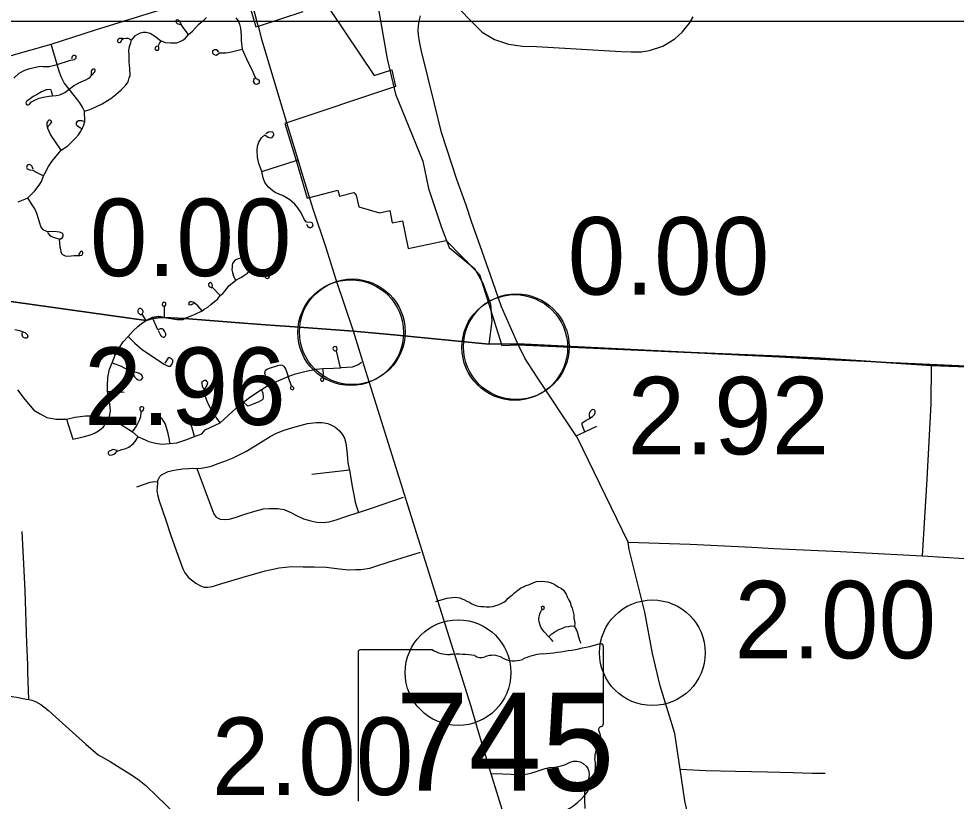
# Model space of a CAD drawing. Extents: x 1729596 to 1934326, y 644115 to 911751.
# Drawn here: x 1788422 to 1801727, y 773601 to 784711 of the extents above; entities that cross this region are included whole.
import ezdxf

# ---------------------------------------------------------------- set-up
doc = ezdxf.new("R2010")
doc.units = 0
for name, color, linetype in [('Default', 7, 'Continuous'), ('GM_X_City_Street', 7, 'Continuous'), ('GM_X_Corporation', 7, 'Continuous'), ('GM_X_County', 7, 'Continuous'), ('GM_X_State_Route', 7, 'Continuous'), ('GM_X_State_Shield', 7, 'Continuous'), ('GM_X_Township', 7, 'Continuous'), ('SC_Scratch1', 7, 'Continuous')]:
    doc.layers.add(name, color=color, linetype=linetype)

msp = doc.modelspace()

# ---------------------------------------------------------------- linework, layer by layer
at = {"layer": 'Default'}
for centre in [(1793134, 780255), (1793134, 780255), (1793156, 780266), (1795462, 780044), (1795462, 780044), (1795483, 780055), (1797415, 775709), (1794657, 775427)]:
    msp.add_circle(centre, 750, dxfattribs=at)
at = {"layer": 'GM_X_City_Street'}
for points in [[(1786111, 783497), (1786161, 783513), (1786229, 783545), (1786322, 783619), (1786378, 783661), (1786427, 783697), (1786487, 783730), (1786569, 783756), (1786939, 783865), (1787087, 783901), (1787342, 783978), (1787586, 784047), (1787860, 784131), (1788123, 784193), (1788314, 784188), (1788881, 784351), (1789511, 784554), (1790304, 784798), (1790967, 785005), (1791652, 785213)], [(1789356, 783400), (1789433, 783423), (1789518, 783458), (1789607, 783505), (1789681, 783549), (1789727, 783577), (1789801, 783637), (1789878, 783702), (1789938, 783762), (1789973, 783813), (1789991, 783871), (1790003, 783904), (1789998, 784006), (1789989, 784098), (1789987, 784196), (1789984, 784256), (1789995, 784319), (1790012, 784368), (1790024, 784407), (1790048, 784434), (1790080, 784471), (1790114, 784494), (1790151, 784511), (1790187, 784519), (1790230, 784520), (1790289, 784507), (1790365, 784458), (1790421, 784413), (1790445, 784397), (1790501, 784374), (1790577, 784367), (1790618, 784368), (1790665, 784369), (1790714, 784389), (1790753, 784408), (1790789, 784437), (1790831, 784488), (1790887, 784537), (1790931, 784580), (1790973, 784629), (1791012, 784663), (1791048, 784692), (1791085, 784728)], [(1791504, 784726), (1791535, 784683), (1791553, 784636), (1791567, 784578), (1791577, 784474), (1791577, 784402), (1791592, 784280), (1791630, 784195), (1791679, 784092), (1791710, 784030), (1791743, 783957), (1791772, 783888), (1791788, 783862), (1791815, 783852), (1791832, 783838), (1791835, 783820), (1791833, 783798), (1791819, 783786), (1791801, 783778), (1791779, 783784), (1791766, 783795), (1791755, 783818), (1791770, 783872)], [(1790831, 784488), (1790754, 784589), (1790727, 784629), (1790719, 784654), (1790709, 784674), (1790689, 784691), (1790668, 784694), (1790656, 784690), (1790651, 784682), (1790655, 784658), (1790669, 784642), (1790700, 784636), (1790722, 784629)], [(1788415, 782110), (1788510, 782150), (1788551, 782167), (1788652, 782266), (1788713, 782346), (1788743, 782401), (1788772, 782479), (1788791, 782516), (1788844, 782611), (1788894, 782686), (1788952, 782759), (1789024, 782843), (1789118, 782906), (1789174, 782964), (1789228, 783014), (1789269, 783061), (1789291, 783092), (1789323, 783148), (1789348, 783207), (1789359, 783254), (1789356, 783400), (1789329, 783456), (1789290, 783516), (1789263, 783556), (1789137, 783711), (1789068, 783802), (1789026, 783888), (1788990, 783979), (1788967, 784062), (1788881, 784351)], [(1789900, 784432), (1789878, 784431), (1789851, 784431), (1789837, 784422), (1789826, 784407), (1789825, 784390), (1789837, 784376), (1789852, 784373), (1789871, 784380), (1789882, 784401), (1789894, 784423), (1789908, 784431), (1789946, 784435), (1789969, 784434), (1789995, 784424), (1790024, 784407)], [(1790398, 784323), (1790374, 784319), (1790361, 784308), (1790356, 784294), (1790355, 784286), (1790361, 784272), (1790382, 784261), (1790401, 784264), (1790408, 784278), (1790411, 784302), (1790407, 784330), (1790419, 784361), (1790445, 784397)], [(1788352, 783865), (1788430, 783939), (1788507, 783981), (1788580, 784005), (1788703, 784035), (1788744, 784037), (1788768, 784035), (1788856, 784035), (1788967, 784062), (1789157, 784124), (1789215, 784133), (1789239, 784154), (1789239, 784170), (1789232, 784185), (1789212, 784191), (1789194, 784189), (1789182, 784173), (1789170, 784140)], [(1791262, 784238), (1791242, 784262), (1791227, 784269), (1791213, 784271), (1791200, 784269), (1791186, 784259), (1791174, 784251), (1791173, 784227), (1791176, 784218), (1791184, 784207), (1791203, 784197), (1791226, 784196), (1791246, 784210), (1791269, 784228), (1791359, 784229), (1791440, 784241), (1791592, 784280)], [(1788901, 783628), (1788892, 783669), (1788888, 783685), (1788876, 783703), (1788857, 783708), (1788826, 783704), (1788811, 783702), (1788744, 783671), (1788683, 783636), (1788626, 783605), (1788583, 783575), (1788533, 783534), (1788525, 783517), (1788528, 783498), (1788538, 783490), (1788554, 783491), (1788573, 783496), (1788604, 783531), (1788641, 783551), (1788670, 783566), (1788712, 783583), (1788749, 783594), (1788795, 783604), (1788851, 783613), (1788896, 783615), (1788953, 783619), (1789007, 783630), (1789075, 783665), (1789137, 783711), (1789197, 783758), (1789274, 783799), (1789340, 783830), (1789376, 783844), (1789415, 783865), (1789430, 783879), (1789455, 783906), (1789477, 783929), (1789488, 783941), (1789502, 783956), (1789509, 783970), (1789506, 783986), (1789493, 783995), (1789477, 783995), (1789463, 783989), (1789455, 783976), (1789452, 783961), (1789452, 783912)], [(1789024, 782843), (1788875, 783066), (1788835, 783151), (1788841, 783186), (1788870, 783216), (1788882, 783231), (1788889, 783239), (1788890, 783244), (1788889, 783250), (1788885, 783255), (1788876, 783263), (1788865, 783269), (1788853, 783269), (1788842, 783262), (1788833, 783251), (1788822, 783232), (1788820, 783215), (1788820, 783194), (1788830, 783153)], [(1789323, 783148), (1789300, 783159), (1789276, 783173), (1789246, 783193), (1789240, 783211), (1789244, 783234), (1789254, 783257), (1789269, 783265), (1789293, 783266), (1789315, 783264), (1789359, 783254)], [(1791871, 782541), (1791831, 782654), (1791812, 782744), (1791806, 782842), (1791812, 782904), (1791831, 782961), (1791865, 783021), (1791917, 783061), (1791963, 783032), (1791992, 783019), (1792019, 783026), (1792042, 783057), (1792044, 783072), (1792027, 783099), (1791998, 783107), (1791965, 783101), (1791927, 783076)], [(1788625, 782574), (1788616, 782601), (1788611, 782614), (1788596, 782633), (1788576, 782642), (1788555, 782639), (1788540, 782627), (1788533, 782599), (1788542, 782581), (1788557, 782573), (1788575, 782568), (1788628, 782561), (1788670, 782534), (1788772, 782479)], [(1791871, 782541), (1792361, 782698), (1792387, 782707)], [(1792505, 781794), (1792527, 781763), (1792545, 781746), (1792569, 781746), (1792586, 781757), (1792599, 781776), (1792597, 781796), (1792586, 781813), (1792570, 781819), (1792508, 781822), (1792477, 781856), (1792445, 781926), (1792422, 781971), (1792385, 782027), (1792341, 782080), (1792271, 782141), (1792177, 782198), (1792061, 782246), (1792027, 782268), (1791966, 782318), (1791917, 782384), (1791892, 782451), (1791871, 782541)], [(1788829, 781675), (1788857, 781639), (1788882, 781622), (1788912, 781608), (1788960, 781594), (1788995, 781586), (1789019, 781588), (1789038, 781599), (1789048, 781614), (1789051, 781624), (1789052, 781639), (1789051, 781649), (1789047, 781656), (1789037, 781666), (1789001, 781680), (1788919, 781689), (1788828, 781685), (1788770, 781715), (1788737, 781762), (1788721, 781810), (1788703, 781869), (1788683, 781930), (1788665, 781982), (1788641, 782025), (1788604, 782084), (1788551, 782167)], [(1788995, 781586), (1788999, 781521), (1789006, 781474), (1789014, 781438), (1789020, 781402), (1789031, 781380), (1789043, 781362), (1789061, 781352), (1789082, 781346), (1789118, 781342), (1789165, 781345), (1789209, 781349), (1789288, 781349), (1789316, 781352), (1789328, 781362), (1789333, 781381), (1789331, 781394), (1789325, 781403), (1789311, 781409), (1789300, 781404), (1789293, 781396), (1789283, 781385), (1789270, 781359)], [(1791600, 781309), (1791613, 781339), (1791616, 781385), (1791619, 781458)], [(1790776, 780453), (1790904, 780507), (1790925, 780515), (1791023, 780562), (1791056, 780587), (1791108, 780616), (1791150, 780652), (1791250, 780736), (1791280, 780781), (1791317, 780810), (1791351, 780849), (1791406, 780917), (1791502, 780999), (1791572, 781038), (1791610, 781059), (1791668, 781101), (1791693, 781125), (1791708, 781142), (1791712, 781181), (1791708, 781209), (1791698, 781236), (1791677, 781269), (1791639, 781296), (1791617, 781304), (1791600, 781309), (1791572, 781311), (1791536, 781302), (1791503, 781286), (1791481, 781267), (1791458, 781236), (1791452, 781219), (1791449, 781190), (1791446, 781148), (1791454, 781106), (1791470, 781058), (1791500, 781004)], [(1791708, 781142), (1791852, 781081), (1791902, 781060), (1791934, 781030), (1791949, 781025), (1791961, 781026), (1791973, 781033), (1791982, 781049), (1791983, 781068), (1791975, 781084), (1791949, 781089), (1791902, 781070)], [(1791280, 780781), (1791168, 780898), (1791173, 780923), (1791166, 780944), (1791154, 780959), (1791139, 780966), (1791129, 780962), (1791120, 780954), (1791113, 780936), (1791119, 780916), (1791136, 780905), (1791163, 780892)], [(1790229, 780426), (1790175, 780517), (1790184, 780538), (1790186, 780546), (1790188, 780554), (1790181, 780568), (1790178, 780577), (1790174, 780583), (1790166, 780589), (1790160, 780593), (1790156, 780596), (1790151, 780599), (1790142, 780598), (1790134, 780595), (1790126, 780590), (1790121, 780585), (1790116, 780579), (1790112, 780570), (1790113, 780562), (1790113, 780557), (1790112, 780550), (1790113, 780545), (1790116, 780539), (1790120, 780531), (1790126, 780526), (1790134, 780521), (1790151, 780514), (1790171, 780514)], [(1790491, 780471), (1790493, 780620), (1790512, 780651), (1790512, 780663), (1790508, 780676), (1790495, 780682), (1790479, 780685), (1790465, 780677), (1790456, 780657), (1790460, 780644), (1790466, 780638), (1790484, 780624)], [(1791023, 780562), (1790964, 780636), (1790914, 780678), (1790896, 780688), (1790873, 780690), (1790854, 780690), (1790840, 780682), (1790831, 780667), (1790837, 780655), (1790855, 780651), (1790874, 780654), (1790888, 780661), (1790907, 780670)], [(1789704, 779043), (1789715, 779089), (1789724, 779146), (1789722, 779192), (1789709, 779277), (1789682, 779417), (1789680, 779501), (1789687, 779615), (1789709, 779735), (1789747, 779826), (1789795, 779948), (1789843, 780028), (1789906, 780123), (1789973, 780198), (1790046, 780282), (1790110, 780341), (1790166, 780385), (1790229, 780426), (1790323, 780455), (1790403, 780463), (1790491, 780471), (1790665, 780443), (1790696, 780441), (1790728, 780441), (1790750, 780442), (1790776, 780453)], [(1790400, 780283), (1790418, 780247), (1790434, 780217), (1790446, 780201), (1790471, 780188), (1790486, 780189), (1790493, 780196), (1790505, 780209), (1790508, 780220), (1790508, 780235), (1790500, 780254), (1790491, 780277), (1790475, 780298), (1790458, 780306), (1790428, 780307), (1790395, 780294), (1790323, 780455)], [(1788369, 780298), (1788433, 780283), (1788485, 780266), (1788520, 780252), (1788540, 780230), (1788546, 780218), (1788551, 780205), (1788546, 780189), (1788545, 780184), (1788532, 780177), (1788521, 780174), (1788515, 780174), (1788488, 780185), (1788482, 780196), (1788475, 780211), (1788472, 780225), (1788470, 780242), (1788474, 780262)], [(1789973, 780198), (1790068, 780107), (1790178, 780010), (1790488, 779809), (1790541, 779778), (1790574, 779776), (1790593, 779804), (1790609, 779841), (1790609, 779864), (1790587, 779889), (1790556, 779901), (1790539, 779887), (1790496, 779823)], [(1792988, 779756), (1792931, 779997), (1792938, 780010), (1792939, 780025), (1792937, 780041), (1792932, 780051), (1792921, 780055), (1792906, 780056), (1792894, 780052), (1792888, 780049), (1792884, 780043), (1792882, 780030), (1792886, 780020), (1792890, 780010), (1792899, 780001), (1792909, 779998), (1792929, 779997)], [(1789747, 779826), (1789876, 779777), (1789971, 779727), (1790031, 779683), (1790065, 779628), (1790092, 779598), (1790118, 779583), (1790147, 779580), (1790165, 779589), (1790181, 779612), (1790179, 779637), (1790166, 779654), (1790136, 779672), (1790095, 779686), (1790047, 779691)], [(1791983, 779520), (1791922, 779641), (1791919, 779660), (1791913, 779682), (1791918, 779697), (1791924, 779721), (1791948, 779737), (1791982, 779752), (1792099, 779789), (1792137, 779795), (1792165, 779794), (1792185, 779775), (1792200, 779756), (1792211, 779733), (1792245, 779631)], [(1792997, 779757), (1793077, 779763), (1793160, 779770), (1793235, 779797), (1793288, 779833)], [(1801247, 777085), (1801313, 778173), (1801372, 779244), (1801375, 779790)], [(1788405, 779442), (1788510, 779307), (1788637, 779155), (1788724, 779103), (1788822, 779051), (1788950, 779024), (1789102, 779024), (1789220, 779052), (1789372, 779073), (1789476, 779073), (1789597, 779060), (1789651, 779051), (1789704, 779043), (1789793, 779002), (1789904, 778933), (1789954, 778896), (1790035, 778844), (1790115, 778777), (1790173, 778753), (1790269, 778708), (1790361, 778684), (1790451, 778673), (1790566, 778679), (1790667, 778689), (1790810, 778738), (1790917, 778780), (1791021, 778816), (1791068, 778874), (1791283, 778975), (1791509, 779180), (1791555, 779219), (1791610, 779266), (1791704, 779339), (1791865, 779449), (1791983, 779520), (1792245, 779631), (1792350, 779669), (1792502, 779709), (1792643, 779738), (1792740, 779744), (1792891, 779750), (1792976, 779755), (1792988, 779756), (1792997, 779757)], [(1792739, 779614), (1792723, 779610), (1792711, 779602), (1792707, 779592), (1792709, 779577), (1792719, 779565), (1792728, 779564), (1792738, 779567), (1792747, 779576), (1792751, 779587), (1792750, 779596), (1792748, 779603), (1792739, 779614), (1792749, 779679), (1792740, 779744)], [(1791283, 778975), (1791186, 779107), (1791153, 779161), (1791126, 779215), (1791092, 779289), (1791069, 779364), (1791056, 779406), (1791052, 779454), (1791071, 779469), (1791085, 779490), (1791098, 779514), (1791105, 779547), (1791093, 779562), (1791080, 779574), (1791057, 779577), (1791046, 779570), (1791030, 779557), (1791018, 779545), (1791019, 779531), (1791025, 779496), (1791031, 779486), (1791050, 779454)], [(1791610, 779266), (1791513, 779380), (1791495, 779419), (1791490, 779457), (1791488, 779505), (1791519, 779531), (1791531, 779542), (1791546, 779561), (1791571, 779602), (1791570, 779613), (1791560, 779631), (1791545, 779639), (1791527, 779639), (1791517, 779636), (1791502, 779628), (1791490, 779609), (1791475, 779582), (1791473, 779556), (1791474, 779531), (1791486, 779505)], [(1792291, 779492), (1792282, 779485), (1792279, 779474), (1792280, 779460), (1792284, 779451), (1792306, 779443), (1792316, 779447), (1792320, 779454), (1792324, 779464), (1792324, 779473), (1792317, 779482), (1792311, 779487), (1792302, 779492), (1792291, 779492), (1792245, 779631)], [(1789682, 779417), (1789776, 779420), (1789920, 779407)], [(1791610, 779266), (1791669, 779216), (1791690, 779221), (1791717, 779229), (1791827, 779271), (1791892, 779311), (1791897, 779340), (1791893, 779389), (1791865, 779449)], [(1790035, 778844), (1790094, 778927), (1790132, 779000), (1790155, 779063), (1790161, 779120), (1790163, 779133), (1790181, 779144), (1790193, 779160), (1790196, 779177), (1790196, 779185), (1790189, 779195), (1790175, 779202), (1790161, 779203), (1790146, 779197), (1790140, 779183), (1790140, 779168), (1790156, 779135)], [(1790917, 778780), (1790877, 778915), (1790767, 779125), (1790752, 779171)], [(1796458, 778846), (1796426, 778917), (1796419, 778943), (1796418, 778975), (1796469, 779005), (1796511, 779030), (1796566, 779062), (1796593, 779090), (1796601, 779115), (1796604, 779144), (1796589, 779157), (1796569, 779165), (1796550, 779155), (1796534, 779140), (1796518, 779105), (1796519, 779073), (1796526, 779038)], [(1789102, 779024), (1789192, 778742), (1789338, 778775), (1789440, 778805), (1789505, 778830), (1789556, 778860), (1789594, 778887), (1789624, 778916), (1789639, 778938), (1789646, 778970), (1789651, 779051)], [(1790566, 778679), (1790564, 778733), (1790544, 778820), (1790503, 778953), (1790458, 779032), (1790398, 779094)], [(1790099, 778063), (1790288, 778133), (1790322, 778136), (1790355, 778139), (1790391, 778134), (1790401, 778164), (1790408, 778184), (1790424, 778212), (1790447, 778235), (1790496, 778260), (1790542, 778283), (1790606, 778297), (1790655, 778308), (1790745, 778322), (1790833, 778326), (1790891, 778331), (1790951, 778327), (1791011, 778332), (1791088, 778342), (1791156, 778360), (1791237, 778391), (1791346, 778428), (1791465, 778477), (1791550, 778517), (1791645, 778567), (1791779, 778646), (1791891, 778716), (1791991, 778779), (1792072, 778822), (1792173, 778863), (1792314, 778908), (1792519, 778963), (1792642, 778980), (1792730, 778980), (1792809, 778966), (1792859, 778941), (1792910, 778918), (1792975, 778860), (1793014, 778811), (1793044, 778754), (1793064, 778684), (1793076, 778577), (1793087, 778469), (1793092, 778412), (1793113, 778316), (1793115, 778305), (1793141, 778155), (1793157, 778048), (1793179, 777953), (1793198, 777849), (1793216, 777788), (1793246, 777702)], [(1796333, 778788), (1796458, 778846), (1796628, 778926)], [(1789817, 778580), (1789783, 778592), (1789759, 778593), (1789727, 778583), (1789703, 778569), (1789692, 778556), (1789692, 778543), (1789695, 778531), (1789704, 778520), (1789716, 778514), (1789746, 778519), (1789785, 778534), (1789821, 778572), (1789848, 778582), (1789887, 778594), (1789941, 778609), (1789983, 778630), (1790045, 778676), (1790074, 778708), (1790115, 778777)], [(1790951, 778327), (1791171, 777731), (1791194, 777674), (1791223, 777634), (1791282, 777606), (1791336, 777599), (1791408, 777607), (1791495, 777628), (1791618, 777671), (1791771, 777721), (1791894, 777752), (1791982, 777758), (1792100, 777757), (1792190, 777743), (1792285, 777700), (1792366, 777658), (1792463, 777613), (1792568, 777582), (1792652, 777562), (1792742, 777558), (1792826, 777567), (1792929, 777595), (1793062, 777643), (1793238, 777699), (1793246, 777702), (1793442, 777768), (1793882, 777919)], [(1792584, 778243), (1793115, 778305)], [(1790391, 778134), (1790387, 778051), (1790382, 778011), (1790391, 777956), (1790414, 777867), (1790468, 777716), (1790509, 777594), (1790578, 777386), (1790658, 777159), (1790751, 776900), (1790777, 776845), (1790832, 776780), (1790937, 776695), (1791003, 776661), (1791054, 776642), (1791106, 776642), (1791170, 776649), (1791259, 776676), (1791606, 776781), (1791919, 776873), (1792011, 776891), (1792118, 776916), (1792297, 776934), (1792459, 776931), (1792613, 776927), (1792783, 776923), (1792974, 776902), (1793100, 776887), (1793202, 776892), (1793276, 776890), (1793407, 776911), (1793502, 776942), (1793667, 776996), (1794123, 777139)], [(1788551, 775488), (1788549, 775542), (1788539, 775845), (1788512, 776595), (1788492, 777063), (1788470, 777429)], [(1797070, 777278), (1797953, 777250), (1798827, 777207), (1799137, 777189), (1800084, 777145), (1801247, 777085), (1801844, 777048), (1803558, 776945), (1803593, 776944)], [(1794341, 776439), (1794370, 776448), (1794451, 776472), (1794498, 776483), (1794535, 776490), (1794578, 776494), (1794616, 776497), (1794651, 776494), (1794683, 776488), (1794712, 776477), (1794740, 776463), (1794779, 776444), (1794818, 776427), (1794842, 776409), (1794875, 776396), (1794909, 776382), (1794948, 776373), (1794981, 776365), (1795025, 776364), (1795058, 776361), (1795107, 776362), (1795149, 776364), (1795195, 776381), (1795228, 776391), (1795269, 776409), (1795306, 776427), (1795338, 776453), (1795366, 776482), (1795402, 776515), (1795430, 776533), (1795459, 776561), (1795507, 776597), (1795544, 776625), (1795575, 776640), (1795624, 776663), (1795670, 776678), (1795709, 776696), (1795771, 776719), (1795838, 776725), (1795886, 776722), (1795932, 776715), (1795976, 776701), (1796020, 776682), (1796065, 776656), (1796088, 776641), (1796124, 776622), (1796153, 776597), (1796171, 776568), (1796189, 776543), (1796207, 776505), (1796226, 776467), (1796246, 776429), (1796259, 776383), (1796277, 776343), (1796290, 776286), (1796298, 776247), (1796302, 776203), (1796308, 776160), (1796313, 776123), (1796311, 776089), (1796321, 776063), (1796331, 776039), (1796345, 776004), (1796365, 775935), (1796386, 775876), (1796399, 775845)], [(1784196, 776473), (1784304, 776457), (1784415, 776425), (1784775, 776295), (1785202, 776135), (1785945, 775831), (1786304, 775696), (1786590, 775596), (1786871, 775480), (1787181, 775362), (1787342, 775300), (1787411, 775274), (1787519, 775244), (1788001, 775154), (1788269, 775099), (1788392, 775079), (1788532, 775051)], [(1796007, 775869), (1795972, 775907), (1795944, 775934), (1795878, 776005), (1795852, 776042), (1795833, 776072), (1795820, 776102), (1795810, 776150), (1795805, 776187), (1795810, 776221), (1795817, 776259), (1795829, 776286), (1795840, 776313), (1795845, 776321), (1795860, 776324), (1795874, 776331), (1795882, 776338), (1795881, 776352), (1795879, 776360), (1795874, 776365), (1795868, 776368), (1795860, 776365), (1795852, 776365), (1795841, 776361), (1795838, 776356), (1795839, 776349), (1795842, 776339), (1795853, 776323)], [(1795944, 775934), (1795987, 775978), (1796044, 776015), (1796087, 776039), (1796128, 776052), (1796177, 776075), (1796228, 776084), (1796263, 776090), (1796311, 776089)], [(1788553, 775432), (1788551, 775488)], [(1788566, 775044), (1788553, 775432)], [(1788532, 775051), (1788566, 775044), (1788608, 775035), (1788660, 775017), (1788735, 774973), (1788780, 774943), (1788844, 774889), (1789044, 774708), (1789373, 774412), (1789549, 774260), (1789720, 774163), (1789825, 774100), (1789963, 774014), (1790039, 773965), (1790129, 773902), (1790224, 773825), (1790392, 773663), (1790495, 773565), (1790720, 773346), (1790822, 773244), (1790886, 773175)], [(1795129, 773990), (1795213, 773994), (1795290, 773990), (1795410, 773985), (1795490, 773982), (1795586, 773981), (1795646, 773988), (1795705, 774002), (1795780, 774029), (1795893, 774068), (1795951, 774080), (1796030, 774087), (1796079, 774093), (1796122, 774103), (1796174, 774120), (1796247, 774154), (1796297, 774168), (1796341, 774172), (1796388, 774162), (1796433, 774139), (1796473, 774101), (1796497, 774065), (1796514, 774021), (1796519, 773985), (1796515, 773940), (1796499, 773878), (1796465, 773780), (1796453, 773723), (1796450, 773664), (1796449, 773613), (1796456, 773496)], [(1797809, 774055), (1798172, 774036), (1798594, 774027), (1799049, 774019), (1799413, 774009), (1799687, 773999), (1799865, 774001)]]:
    msp.add_lwpolyline(points, dxfattribs=at)
at = {"layer": 'GM_X_Corporation'}
for points in [[(1791612, 785199), (1791786, 784595), (1791823, 784606), (1792459, 784812)], [(1792848, 784829), (1793468, 783905), (1793718, 783987), (1793735, 783894), (1793754, 783819), (1793758, 783789), (1793768, 783761), (1793769, 783748), (1792200, 783224), (1792361, 782698), (1792515, 782165), (1792950, 782279), (1792976, 782192), (1793178, 782246), (1793210, 782204), (1793248, 782040), (1793540, 781957), (1793687, 781987), (1793723, 781813), (1793870, 781843), (1793949, 781451), (1794488, 781561), (1794963, 781078), (1795276, 780074), (1795510, 780081), (1797967, 779971), (1799216, 779912), (1799794, 779878), (1803634, 779704)]]:
    msp.add_lwpolyline(points, dxfattribs=at)
at = {"layer": 'GM_X_County'}
for points in [[(1788100, 780727), (1790229, 780426), (1790317, 780468), (1790410, 780483), (1790491, 780471), (1790776, 780453), (1791556, 780394), (1791923, 780367), (1792339, 780337), (1793171, 780273), (1793746, 780223), (1795095, 780091), (1795507, 780094), (1797967, 779971), (1799218, 779920), (1799802, 779890), (1801375, 779790), (1803634, 779704)], [(1803634, 779704), (1801375, 779790), (1799802, 779890), (1799218, 779920), (1797967, 779971), (1795507, 780094), (1795095, 780091), (1793746, 780223), (1793171, 780273), (1792339, 780337), (1791923, 780367), (1791556, 780394), (1790776, 780453), (1790491, 780471), (1790410, 780483), (1790317, 780468), (1790229, 780426), (1788100, 780727)]]:
    msp.add_lwpolyline(points, dxfattribs=at)
at = {"layer": 'GM_X_State_Route'}
for points in [[(1791821, 784611), (1791757, 784842), (1791666, 785163)], [(1794389, 785145), (1794886, 784632), (1795001, 784522), (1795176, 784416), (1795374, 784351), (1795569, 784322), (1795771, 784315), (1796971, 784245), (1797112, 784239), (1797258, 784243), (1797375, 784261), (1797561, 784324), (1797734, 784427), (1797838, 784522), (1797943, 784647), (1797995, 784740)], [(1794118, 784339), (1794108, 784387), (1794096, 784481), (1794092, 784545), (1794094, 784609), (1794105, 784679), (1794124, 784754)], [(1792525, 782253), (1792445, 782515), (1792387, 782707), (1792229, 783233), (1791879, 784404), (1791823, 784606), (1791821, 784611)], [(1795507, 780094), (1795485, 780137), (1795271, 780621), (1795152, 780977), (1794999, 781404), (1794849, 781834), (1794774, 782063), (1794638, 782430), (1794422, 783094), (1794321, 783501), (1794234, 783865), (1794136, 784253), (1794118, 784339)], [(1792781, 781471), (1792600, 782008), (1792525, 782253)], [(1793171, 780273), (1792928, 781005), (1792811, 781382), (1792781, 781471)], [(1793373, 779630), (1793325, 779785), (1793171, 780273)], [(1797988, 773106), (1797874, 773609), (1797809, 774055), (1797734, 774564), (1797526, 775241), (1797415, 775699), (1797309, 776284), (1797086, 777175), (1797070, 777278), (1796346, 778768), (1796333, 778788), (1795778, 779621), (1795604, 779893), (1795507, 780094)], [(1794934, 774636), (1794841, 774945), (1794370, 776448), (1793373, 779630)], [(1795323, 773347), (1795129, 773990), (1794934, 774636)]]:
    msp.add_lwpolyline(points, dxfattribs=at)
at = {"layer": 'GM_X_State_Shield'}
for p, q in [((1796719, 774697), (1796719, 775803)), ((1793238, 775714), (1793238, 773601)), ((1794292, 775750), (1793273, 775750)), ((1796718, 774698), (1796719, 774697))]:
    msp.add_line(p, q, dxfattribs=at)
for centre, major_axis, start_param, end_param in [((1795479, 778632), (3691, 0), 4.814394, 5.042369), ((1796680, 775807), (38.7, 0), 6.141152, 7.989035), ((1793278, 775719), (40.3, 0), 1.712693, 3.28349), ((1794535, 775996), (391, 0), 4.042523, 4.731795), ((1794664, 774564), (1404, 0), 1.404758, 1.657858), ((1794983, 775730), (113, 0), 3.836095, 5.185415), ((1795149, 775485), (235, 0), 0.950623, 2.079405), ((1795950, 775105), (743, 0), 1.699011, 2.107814), ((1795451, 775820), (282, 0), 4.081561, 5.145723), ((1796710, 774616), (60, 0), 1.883978, 3.671073), ((1796328, 774476), (360, 0), 5.934695, 6.695948), ((1796677, 774693), (41.5, 0), 5.05454, 6.418171), ((1796858, 774235), (262, 0), 2.387724, 3.262537), ((1795686, 774094), (923, 0), 5.101752, 6.440018)]:
    msp.add_ellipse(centre, major_axis=major_axis, ratio=0.8, start_param=start_param, end_param=end_param, dxfattribs=at)
at = {"layer": 'GM_X_Township'}
for points in [[(1793510, 784951), (1793649, 784141), (1793768, 783640), (1794157, 782687), (1794235, 782300), (1794422, 781746), (1794530, 781465), (1794889, 781166), (1795007, 780959), (1795116, 780658), (1795136, 780423), (1795095, 780091)], [(1795507, 780094), (1795095, 780091)]]:
    msp.add_lwpolyline(points, dxfattribs=at)
at = {"layer": 'SC_Scratch1'}
msp.add_lwpolyline([(1730291, 784675), (1926541, 784675), (1926541, 650175), (1730291, 650175)], close=True, dxfattribs=at)

# ---------------------------------------------------------------- texts
at = {"layer": 'Default'}
for s, p in [('0.00', (1789431, 781057)), ('0.00', (1796212, 780794)), ('2.96', (1789349, 778944)), ('2.92', (1797062, 778526)), ('2.00', (1798579, 775630)), ('2.00', (1791161, 773690))]:
    msp.add_text(s, height=1100, dxfattribs=at).set_placement(p)
at = {"layer": 'GM_X_State_Shield'}
msp.add_text('745', height=1392.2, dxfattribs=at).set_placement((1793770, 773750))

doc.saveas('drawing.dxf')
